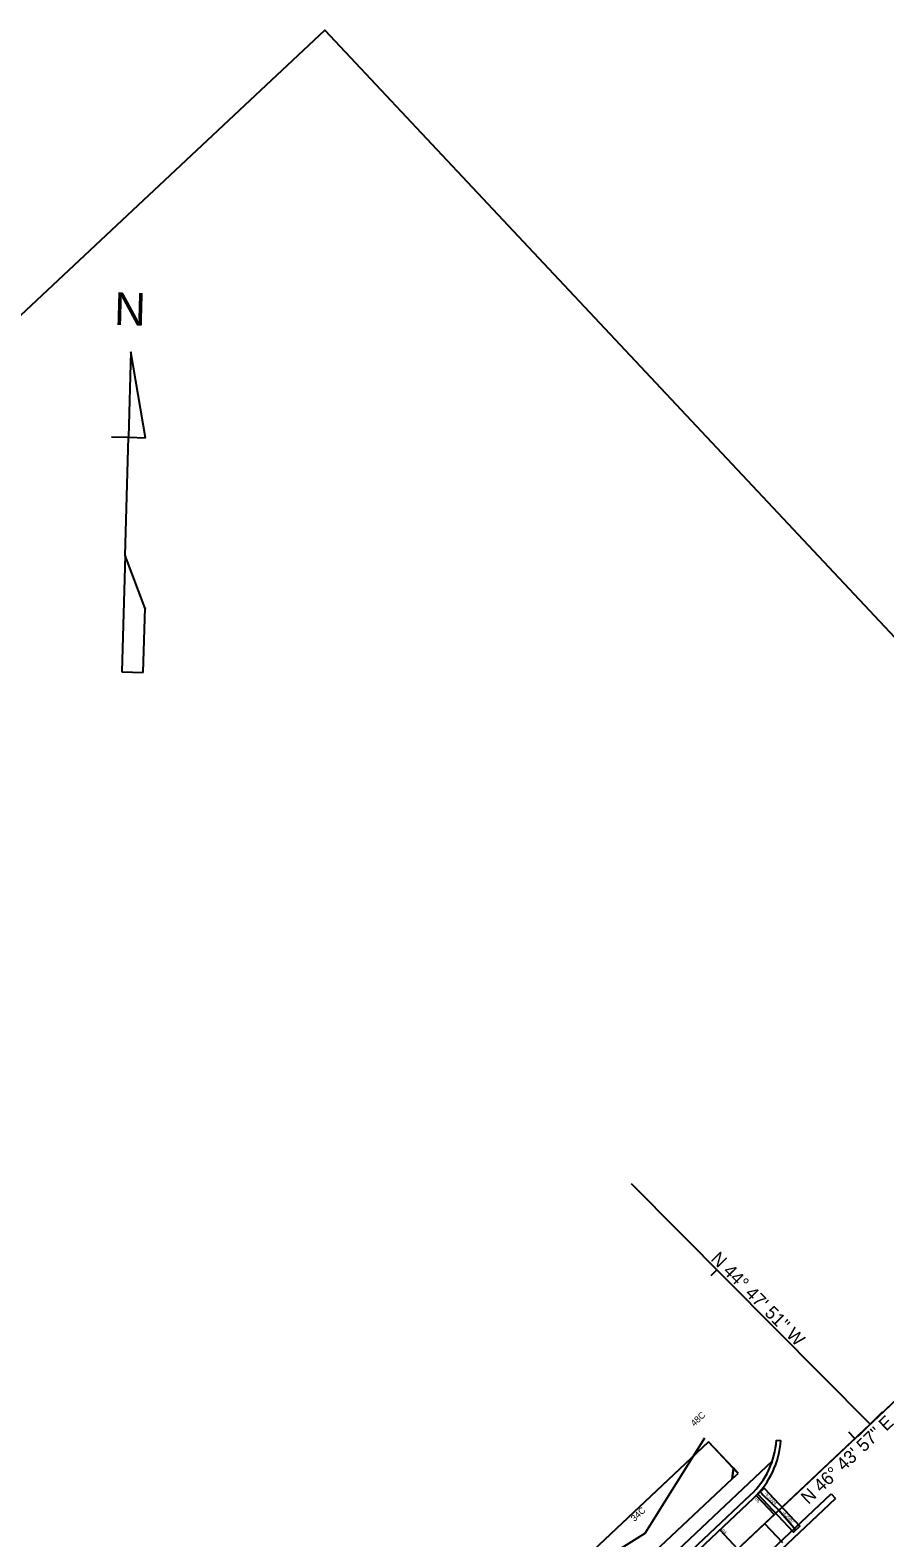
# Model space of a CAD drawing. Extents: x 1623239 to 1625698, y 1118659 to 1120751.
# Drawn here: x 1624485 to 1624877, y 1120033 to 1120726 of the extents above; entities that cross this region are included whole.
import ezdxf

# ---------------------------------------------------------------- set-up
doc = ezdxf.new("R2010")
doc.units = 0
for name, color, linetype in [('RD_HC_Cl', 7, 'Continuous'), ('RD_HC_Data', 7, 'Continuous'), ('RD_HC_Data_Tic', 7, 'Continuous'), ('RD_PD_ALT1_TX', 7, 'Continuous'), ('RD_PD_BOC', 7, 'Continuous'), ('RD_PD_CstnLmt', 7, 'Continuous'), ('RD_PD_CstnLmt_TX', 7, 'Continuous'), ('RD_PD_Final_TrvlWay', 7, 'Continuous'), ('RD_PD_PaintMed', 7, 'Continuous'), ('RD_PD_PaveShd', 7, 'Continuous'), ('RD_PD_RW', 7, 'Continuous'), ('RD_PD_SW', 7, 'Continuous'), ('RD_QTY_Clear_Grub', 7, 'Continuous'), ('RD_SHT_ShtClip', 7, 'Continuous'), ('RD_SHT_TX', 7, 'Continuous'), ('RD_TX_Pipe_ElevEX', 7, 'Continuous')]:
    doc.layers.add(name, color=color, linetype=linetype)

msp = doc.modelspace()

# ---------------------------------------------------------------- linework, layer by layer
at = {"layer": 'RD_HC_Cl'}
for p, q in [((1624678.65, 1119905.11), (1625124.67, 1120324.94)), ((1624870.49, 1120085.68), (1625124.67, 1120324.94)), ((1624870.49, 1120085.68), (1624760.81, 1120196.14)), ((1624678.65, 1119905.11), (1624870.49, 1120085.68))]:
    msp.add_line(p, q, dxfattribs=at)
at = {"layer": 'RD_HC_Data_Tic'}
for p, q in [((1624800.03, 1120156.64), (1624797.19, 1120153.83)), ((1624870.49, 1120085.68), (1624864.81, 1120080.05)), ((1624870.49, 1120085.68), (1624876.17, 1120091.32)), ((1624863.45, 1120079.05), (1624860.7, 1120081.96))]:
    msp.add_line(p, q, dxfattribs=at)
at = {"layer": 'RD_PD_ALT1_TX'}
for p, q in [((1624818.08, 1120052.83), (1624826.31, 1120044.1)), ((1624801.34, 1120037.07), (1624809.56, 1120028.33)), ((1624821.94, 1120039.98), (1624830.17, 1120031.25))]:
    msp.add_line(p, q, dxfattribs=at)
at = {"layer": 'RD_PD_BOC'}
for p, q in [((1624827.4, 1120078.3), (1624829.4, 1120078.17)), ((1624669.06, 1119915.31), (1624815.54, 1120053.18))]:
    msp.add_line(p, q, dxfattribs=at)
msp.add_arc((1624789.49, 1120080.85), 38, 313.26746, 356.15478, dxfattribs=at)
at = {"layer": 'RD_PD_CstnLmt'}
for p, q in [((1624767.03, 1120035.59), (1624794.47, 1120079.38)), ((1624723.78, 1120008.58), (1624767.03, 1120035.59))]:
    msp.add_line(p, q, dxfattribs=at)
at = {"layer": 'RD_PD_Final_TrvlWay'}
msp.add_line((1624670.43, 1119913.85), (1624816.91, 1120051.72), dxfattribs=at)
msp.add_arc((1624789.49, 1120080.85), 40, 313.26746, 356.15478, dxfattribs=at)
at = {"layer": 'RD_PD_PaintMed'}
for p, q in [((1624678.65, 1119905.11), (1624844.95, 1120061.65)), ((1624811.67, 1120015.21), (1624852.49, 1120053.64))]:
    msp.add_line(p, q, dxfattribs=at)
at = {"layer": 'RD_PD_PaveShd'}
for p in [(1624688.24, 1119894.91), (1624852.49, 1120053.64)]:
    msp.add_line(p, (1624854.55, 1120051.45), dxfattribs=at)
at = {"layer": 'RD_PD_RW'}
for p in [(1624647.87, 1119937.94), (1624809.84, 1120063.06)]:
    msp.add_line(p, (1624796.19, 1120077.55), dxfattribs=at)
at = {"layer": 'RD_PD_SW'}
msp.add_line((1624665.98, 1119918.59), (1624825.51, 1120068.75), dxfattribs=at)
at = {"layer": 'RD_QTY_Clear_Grub'}
for p, q in [((1624796.19, 1120077.55), (1624654.03, 1119943.73)), ((1624807.59, 1120065.44), (1624796.19, 1120077.55)), ((1624807.12, 1120060.5), (1624807.59, 1120065.44)), ((1624807.59, 1120065.44), (1624807.12, 1120060.5)), ((1624809.84, 1120063.06), (1624807.59, 1120065.44)), ((1624660.93, 1119923.47), (1624807.12, 1120060.5)), ((1624807.12, 1120060.5), (1624809.84, 1120063.06))]:
    msp.add_line(p, q, dxfattribs=at)
at = {"layer": 'RD_SHT_ShtClip'}
msp.add_lwpolyline([(1623307.11, 1119494.91), (1624620.05, 1120726.24), (1625372.53, 1119923.88), (1624059.58, 1118692.55)], close=True, dxfattribs=at)
at = {"layer": 'RD_SHT_TX'}
for p, q in [((1624530.89, 1120578.35), (1624529.79, 1120539.16)), ((1624537.63, 1120538.94), (1624530.89, 1120578.35)), ((1624530.89, 1120578.35), (1624530.89, 1120578.35)), ((1624521.96, 1120539.38), (1624529.79, 1120539.16)), ((1624528.28, 1120484.79), (1624529.79, 1120539.16)), ((1624529.79, 1120539.16), (1624537.63, 1120538.94)), ((1624537.63, 1120538.94), (1624537.64, 1120539.41)), ((1624528.28, 1120484.79), (1624526.79, 1120431.4)), ((1624537.4, 1120460.52), (1624528.28, 1120484.79)), ((1624536.58, 1120431.13), (1624537.41, 1120460.79)), ((1624537.41, 1120460.79), (1624537.4, 1120460.52)), ((1624526.79, 1120431.4), (1624536.58, 1120431.13))]:
    msp.add_line(p, q, dxfattribs=at)
at = {"layer": 'RD_TX_Pipe_ElevEX'}
for q in [(1624821.18, 1120053.24), (1624835.29, 1120038.34)]:
    msp.add_line((1624828.52, 1120046.18), q, dxfattribs=at)
msp.add_lwpolyline([(1624818.81, 1120053.52), (1624821.73, 1120056.26), (1624838.18, 1120038.79), (1624835.26, 1120036.04)], close=True, dxfattribs=at)
msp.add_lwpolyline([(1624819.91, 1120054.55), (1624820.45, 1120053.99), (1624820.45, 1120053.98), (1624820.45, 1120053.98), (1624820.65, 1120053.77), (1624821.18, 1120053.24), (1624828.67, 1120046.04), (1624833.09, 1120040.88), (1624835.29, 1120038.34), (1624836.18, 1120036.91)], dxfattribs=at)

# ---------------------------------------------------------------- texts
at = {"layer": 'RD_HC_Data'}
for s, rotation, p in [('N 44%%d 47\' 51" W', 314.79754, (1624796.87, 1120161.25)), ('N 46%%d 43\' 57" E', 43.26746, (1624842.04, 1120048.5))]:
    msp.add_text(s, height=6, rotation=rotation, dxfattribs=at).set_placement(p)
at = {"layer": 'RD_PD_ALT1_TX'}
for s, p in [('-05', (1624816.93, 1120051.58)), ('-04', (1624801.54, 1120037.11))]:
    msp.add_text(s, height=1.5, rotation=313.26746, dxfattribs=at).set_placement(p)
at = {"layer": 'RD_PD_CstnLmt_TX'}
for s, p in [('48C', (1624789.68, 1120084.47)), ('34C', (1624762.23, 1120040.69))]:
    msp.add_text(s, height=3, rotation=43.26746, dxfattribs=at).set_placement(p)
at = {"layer": 'RD_SHT_TX'}
msp.add_text('N', height=15, rotation=358.40226, dxfattribs=at).set_placement((1624523.08, 1120590.79))
at = {"layer": 'RD_TX_Pipe_ElevEX'}
for s, p in [('-5.0324', (1624821.89, 1120053.54)), ('-4.2987', (1624829.95, 1120045.06))]:
    msp.add_text(s, height=1.5, rotation=313.26746, dxfattribs=at).set_placement(p)

doc.saveas('drawing.dxf')
